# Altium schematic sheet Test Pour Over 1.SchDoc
size Tabloid; SheetNumber: 1; SheetTotal: 1; ENG_APP_DATE: --/--/--; DSN_APP_DATE: --/--/--; CHK_APP_DATE: --/--/--
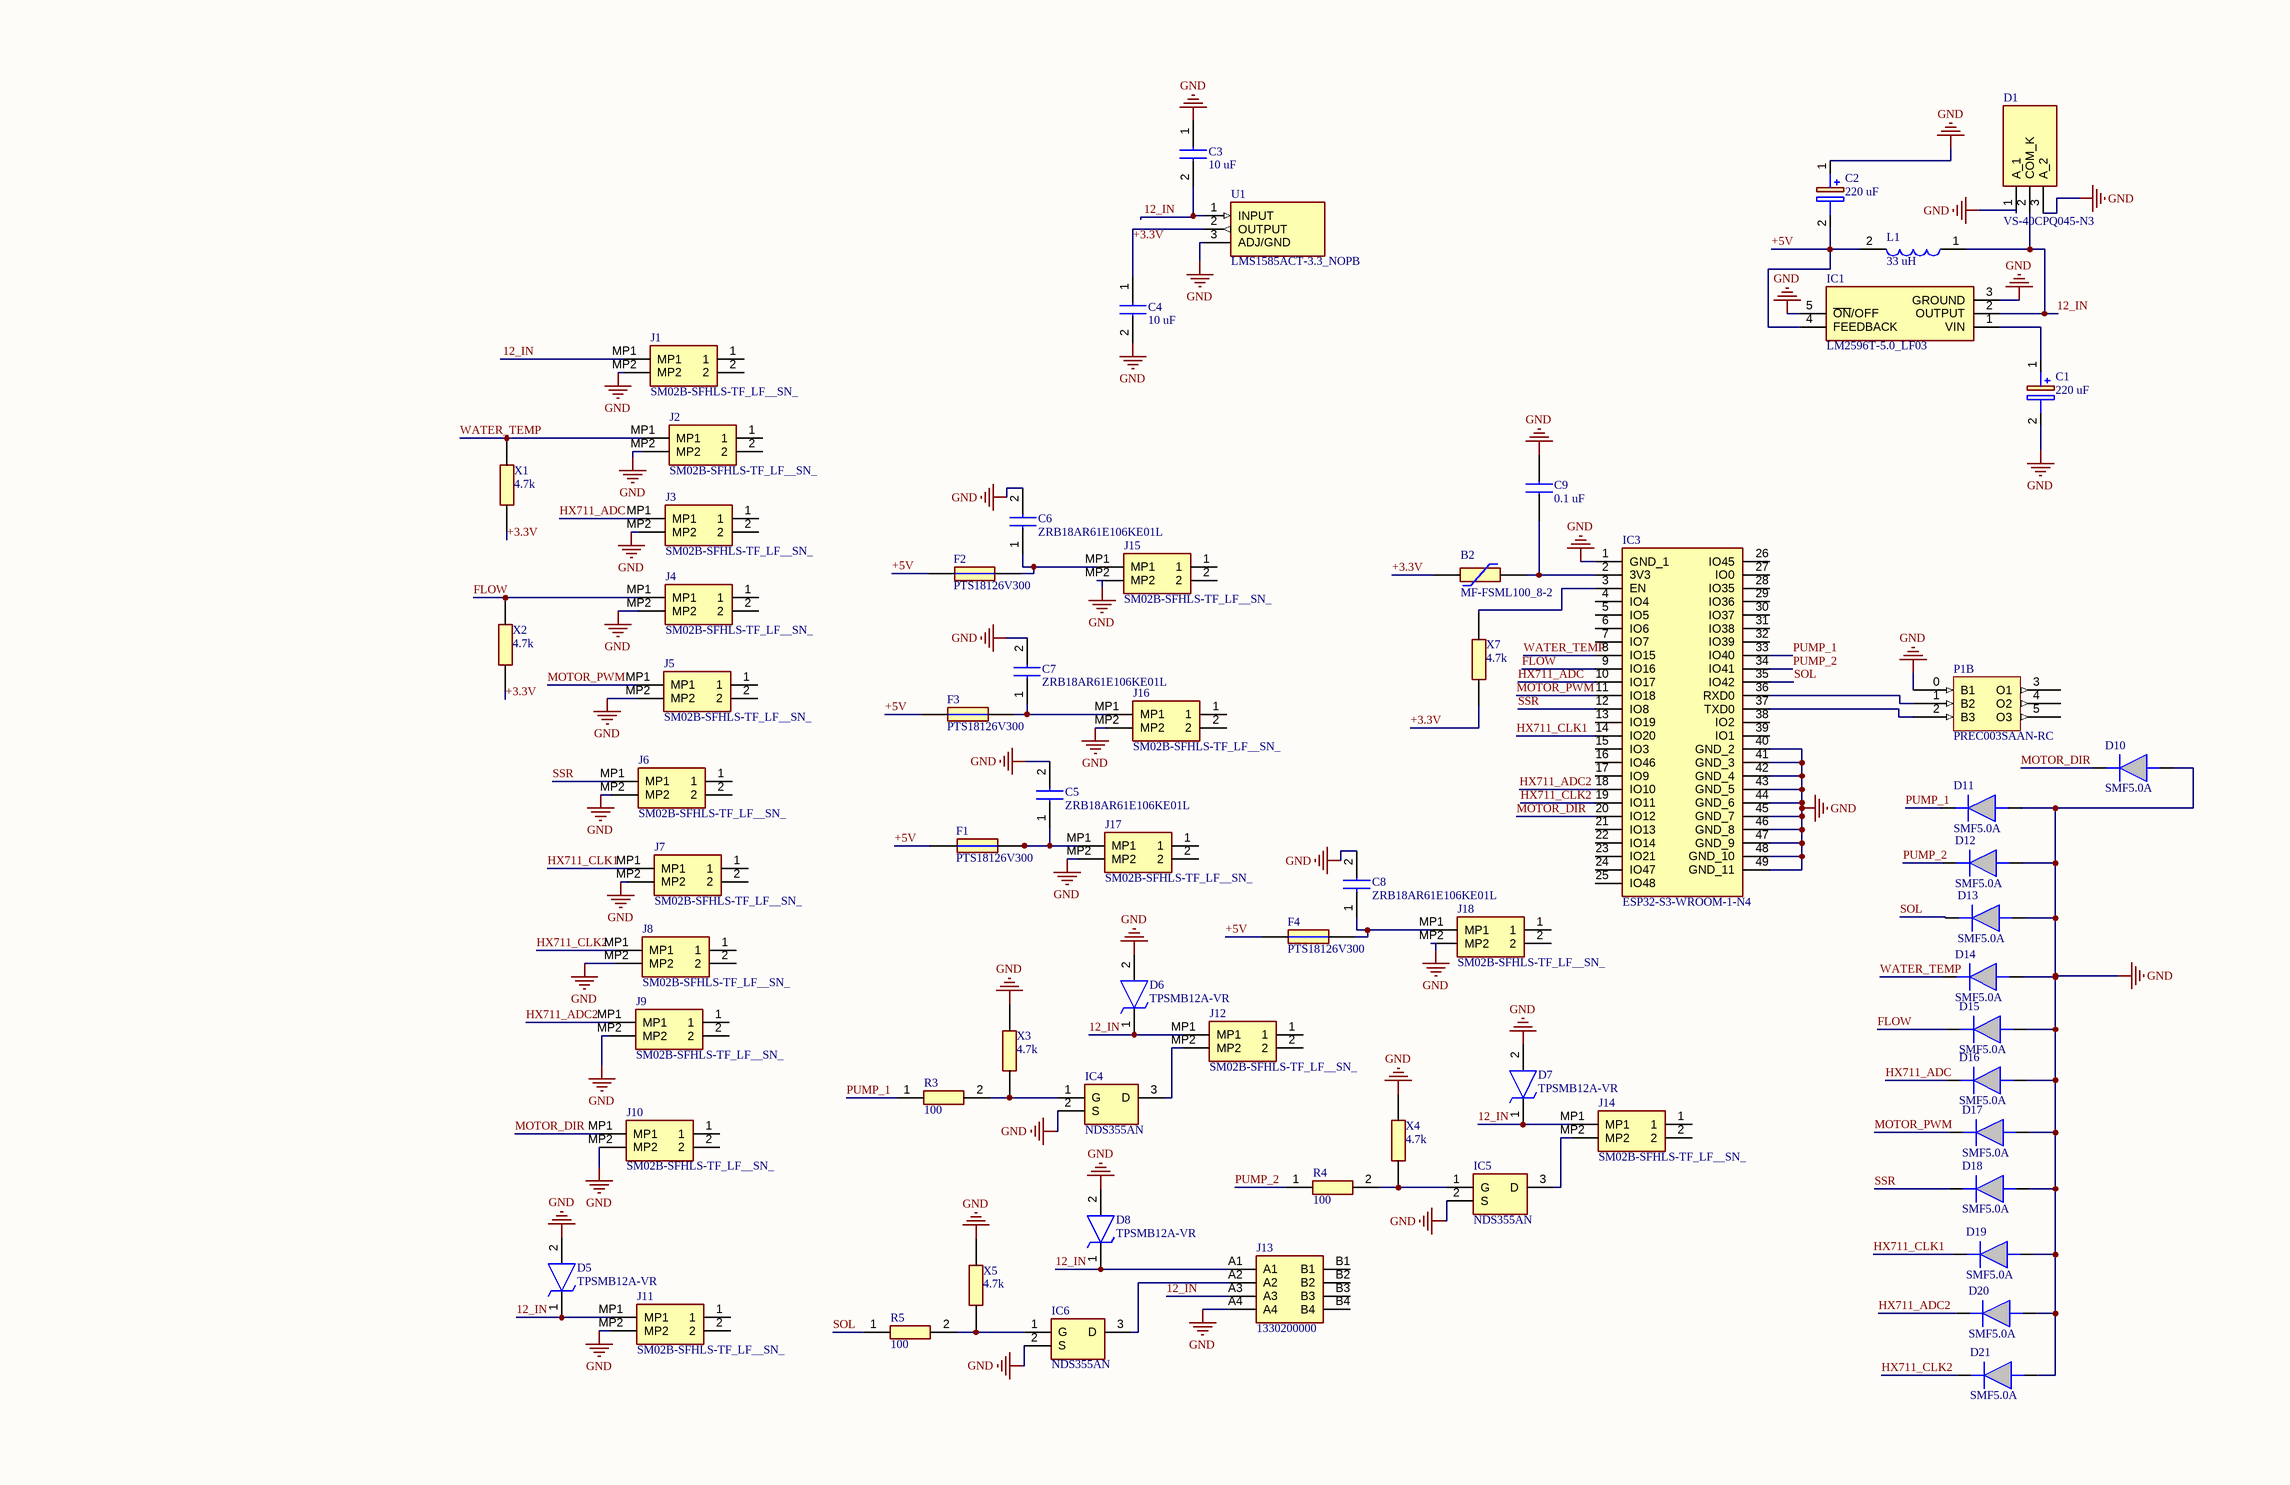
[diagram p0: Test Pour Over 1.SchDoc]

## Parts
B2  MF-FSML100_8-2  [FUSC1608X70N]
C1  220 uF  [EEHZT1E331UP]
C2  220 uF  [EEHZT1E331UP]
C3  10 uF  [ZRB18x]
C4  10 uF  [ZRB18x]
C5  ZRB18AR61E106KE01L  [ZRB18x]
C6  ZRB18AR61E106KE01L  [ZRB18x]
C7  ZRB18AR61E106KE01L  [ZRB18x]
C8  ZRB18AR61E106KE01L  [ZRB18x]
C9  0.1 uF  [CAPC2012X125N]
D1  VS-40CPQ045-N3  [TO546P531X1558X2499-3P]
D5  TPSMB12A-VR  [DIOM5436X244N]
D6  TPSMB12A-VR  [DIOM5436X244N]
D7  TPSMB12A-VR  [DIOM5436X244N]
D8  TPSMB12A-VR  [DIOM5436X244N]
D10  SMF5.0A  [SODFL3618X110N]
D11  SMF5.0A  [SODFL3618X110N]
D12  SMF5.0A  [SODFL3618X110N]
D13  SMF5.0A  [SODFL3618X110N]
D14  SMF5.0A  [SODFL3618X110N]
D15  SMF5.0A  [SODFL3618X110N]
D16  SMF5.0A  [SODFL3618X110N]
D17  SMF5.0A  [SODFL3618X110N]
D18  SMF5.0A  [SODFL3618X110N]
D19  SMF5.0A  [SODFL3618X110N]
D20  SMF5.0A  [SODFL3618X110N]
D21  SMF5.0A  [SODFL3618X110N]
F1  PTS18126V300  [FUSC4632X120N]
F2  PTS18126V300  [FUSC4632X120N]
F3  PTS18126V300  [FUSC4632X120N]
F4  PTS18126V300  [FUSC4632X120N]
IC1  LM2596T-5.0_LF03  [TO170P470X1028X2142-5P]
IC3  ESP32-S3-WROOM-1-N4  [ESP32S3WROOM1N4]
IC4  NDS355AN  [SOT95P251X112-3N]
IC5  NDS355AN  [SOT95P251X112-3N]
IC6  NDS355AN  [SOT95P251X112-3N]
J1  SM02B-SFHLS-TF_LF__SN_  [SM02BSFHLSTFLFSN]
J2  SM02B-SFHLS-TF_LF__SN_  [SM02BSFHLSTFLFSN]
J3  SM02B-SFHLS-TF_LF__SN_  [SM02BSFHLSTFLFSN]
J4  SM02B-SFHLS-TF_LF__SN_  [SM02BSFHLSTFLFSN]
J5  SM02B-SFHLS-TF_LF__SN_  [SM02BSFHLSTFLFSN]
J6  SM02B-SFHLS-TF_LF__SN_  [SM02BSFHLSTFLFSN]
J7  SM02B-SFHLS-TF_LF__SN_  [SM02BSFHLSTFLFSN]
J8  SM02B-SFHLS-TF_LF__SN_  [SM02BSFHLSTFLFSN]
J9  SM02B-SFHLS-TF_LF__SN_  [SM02BSFHLSTFLFSN]
J10  SM02B-SFHLS-TF_LF__SN_  [SM02BSFHLSTFLFSN]
J11  SM02B-SFHLS-TF_LF__SN_  [SM02BSFHLSTFLFSN]
J12  SM02B-SFHLS-TF_LF__SN_  [SM02BSFHLSTFLFSN]
J13  1330200000  [1330200000]
J14  SM02B-SFHLS-TF_LF__SN_  [SM02BSFHLSTFLFSN]
J15  SM02B-SFHLS-TF_LF__SN_  [SM02BSFHLSTFLFSN]
J16  SM02B-SFHLS-TF_LF__SN_  [SM02BSFHLSTFLFSN]
J17  SM02B-SFHLS-TF_LF__SN_  [SM02BSFHLSTFLFSN]
J18  SM02B-SFHLS-TF_LF__SN_  [SM02BSFHLSTFLFSN]
L1  33 uH  [INDPM8680X400N]
P1  PREC003SAAN-RC  [PCBComponent_1]  (part B of 2)
R3  100  [RESC2012X55N]
R4  100  [RESC2012X55N]
R5  100  [RESC2012X55N]
U1  LMS1585ACT-3.3_NOPB  [TO254P470X1028X1955-3P]
X1  4.7k  [RESC2012X65N]
X2  4.7k  [RESC2012X65N]
X3  4.7k  [RESC2012X65N]
X4  4.7k  [RESC2012X65N]
X5  4.7k  [RESC2012X65N]
X7  4.7k  [RESC2012X65N]

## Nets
GND: C1.2(-) C2.1(+) C3.1 C4.2 C5.2 C6.2 C7.2 C8.2 C9.1 D1.1(A_1) D1.3(A_2) D5.2(A) D6.2(A) D7.2(A) D8.2(A) D10.2(A) D11.2(A) D12.2(A) D13.2(A) D14.2(A) D15.2(A) D16.2(A) D17.2(A) D18.2(A) D19.2(A) D20.2(A) D21.2(A) IC1.3(GROUND) IC1.5(~{ON}/OFF) IC3.1(GND_1) IC3.40(GND_2) IC3.41(GND_3) IC3.42(GND_4) IC3.43(GND_5) IC3.44(GND_6) IC3.45(GND_7) IC3.46(GND_8) IC3.47(GND_9) IC3.48(GND_10) IC3.49(GND_11) IC4.2(S) IC5.2(S) IC6.2(S) J1.MP2 J2.MP2 J3.MP2 J4.MP2 J5.MP2 J6.MP2 J7.MP2 J8.MP2 J9.MP2 J10.MP2 J11.MP2 J13.A4 J15.MP2 J16.MP2 J17.MP2 J18.MP2 P1.0(B1) U1.3(ADJ/GND) X3.2 X4.2 X5.2
12_IN: C3.2 D1.2(COM_K) D5.1(K) D6.1(K) D7.1(K) D8.1(K) IC1.2(OUTPUT) J1.MP1 J11.MP1 J12.MP1 J13.A1 J13.A3 J14.MP1 L1.1 U1.1(INPUT)
+3.3V: B2.1 C4.1 U1.2(OUTPUT) X1.2 X2.2 X7.2
+5V: C2.2(-) F1.1 F2.1 F3.1 F4.1 IC1.4(FEEDBACK) L1.2
FLOW: D15.1(K) IC3.9(IO16) J4.MP1 X2.1
HX711_ADC: D16.1(K) IC3.10(IO17) J3.MP1
HX711_ADC2: D20.1(K) IC3.18(IO10) J9.MP1
HX711_CLK1: D19.1(K) IC3.14(IO20) J7.MP1
HX711_CLK2: D21.1(K) IC3.19(IO11) J8.MP1
MOTOR_DIR: D10.1(K) IC3.20(IO12) J10.MP1
MOTOR_PWM: D17.1(K) IC3.11(IO18) J5.MP1
PUMP_1: D11.1(K) IC3.33(IO40) R3.1
PUMP_2: D12.1(K) IC3.34(IO41) R4.1
SOL: D13.1(K) IC3.35(IO42) R5.1
SSR: D18.1(K) IC3.12(IO8) J6.MP1
WATER_TEMP: D14.1(K) IC3.8(IO15) J2.MP1 X1.1
NetB2_2: B2.2 C9.2 IC3.2(3V3)
NetC1_1: C1.1(+) IC1.1(VIN)
NetC5_1: C5.1 F1.2 J17.MP1
NetC6_1: C6.1 F2.2 J15.MP1
NetC7_1: C7.1 F3.2 J16.MP1
NetC8_1: C8.1 F4.2 J18.MP1
NetIC3_3: IC3.3(EN) X7.1
NetIC3_36: IC3.36(RXD0) P1.1(B2)
NetIC3_37: IC3.37(TXD0) P1.2(B3)
NetIC4_1: IC4.1(G) R3.2 X3.1
NetIC4_3: IC4.3(D) J12.MP2
NetIC5_1: IC5.1(G) R4.2 X4.1
NetIC5_3: IC5.3(D) J14.MP2
NetIC6_1: IC6.1(G) R5.2 X5.1
NetIC6_3: IC6.3(D) J13.A2

Not connected (* = marked no-connect by the designer): IC3 4(IO4) 5(IO5) 6(IO6) 7(IO7) 13(IO19) 15(IO3) 16(IO46) 17(IO9) 21(IO13) 22(IO14) 23(IO21) 24(IO47) 25(IO48) 26(IO45) 27(IO0) 28(IO35) 29(IO36) 30(IO37) 31(IO38) 32(IO39) 38(IO2) 39(IO1); J1 1 2; J2 1 2; J3 1 2; J4 1 2; J5 1 2; J6 1 2; J7 1 2; J8 1 2; J9 1 2; J10 1 2; J11 1 2; J12 1 2; J13 B1 B2 B3 B4; J14 1 2; J15 1 2; J16 1 2; J17 1 2; J18 1 2; P1 3(O1) 4(O2) 5(O3)

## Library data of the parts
B2 = MF-FSML100_8-2: Resettable Fuses - PPTC 8V     1A; Manufacturer_Name: Bourns; Manufacturer_Part_Number: MF-FSML100/8-2; Geometry.Height: 0.7mm
C1 C2 = EEE-TP1C221AP: Capacitor Polarised; Manufacturer_Name: Panasonic
C3 C4 = ZRB18AR61E106KE01L: Manufacturer_Name: Murata Electronics
C5-C8 = ZRB18AR61E106KE01L: Capacitor; Manufacturer_Name: Murata Electronics
C9 = 885382207007: WCAP-CSST Soft Termination MLCC X7R0805104K050DFCT1S000; SMT Chip; 100 nF +/- 10%; 50 V(DC); -55C / +125C; size 0805; LxWxH 2.0 x 1.25 x 1.25; Term. Ag-Polymer/Ni/Sn; Manufacturer_Name: Wurth Elektronik; Geometry.Height: 1.25mm
D1 = VS-40CPQ045-N3: Diode; Manufacturer_Name: Vishay
D5-D8 = TPSMB12A-VR: TVS Diode (Uni-directional); Manufacturer_Name: LITTELFUSE
D10-D21 = SMF5.0A: LITTELFUSE - SMF5.0A - TVS DIODE, 200W, 5V, UNIDIR, SOD-123FL; Geometry.Height: 1.1mm
F1-F4 = PTS18126V300: PPTC SMD 1812 6V 3.0A; Manufacturer_Name: Eaton; Geometry.Height: 1.2mm
IC1 = LM2596T-5.0_LF03: Integrated Circuit; Manufacturer_Name: Texas Instruments; Manufacturer_Part_Number: LM2596T-5.0/LF03
IC3 = ESP32-S3-WROOM-1-N4: Integrated Circuit; Manufacturer_Name: Espressif Systems
IC4-IC6 = NDS355AN: Integrated Circuit; Manufacturer_Name: onsemi
J1-J12 J14-J18 = SM02B-SFHLS-TF_LF__SN_: CONN HEADER SMD R/A 2POS 1.8MM; Manufacturer_Name: JST (JAPAN SOLDERLESS TERMINALS); Manufacturer_Part_Number: SM02B-SFHLS-TF(LF)(SN); Geometry.Height: 3mm
J13 = 1330200000: Connector; Manufacturer_Name: Weidmuller
L1 = F1F2-0804-330M: Inductor; Manufacturer_Name: Bel
P1 = PREC003SAAN-RC: ESP32 USB Connector
R3-R5 = TNPW0805100RBEEA: Resistor; Manufacturer_Name: Vishay
U1 = LMS1585ACT-3.3_NOPB: Undefined or Miscellaneous; Manufacturer_Name: Texas Instruments; Manufacturer_Part_Number: LMS1585ACT-3.3/NOPB
X1-X5 X7 = CPF0805B4K7E1: Manufacturer_Name: TE Connectivity; Geometry.Height: 0.65mm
